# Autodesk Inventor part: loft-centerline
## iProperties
Shininess: 77.0
Angle Display Precision: 2
Document Length Units: 11269
Document Angle Units: 11279
Document Time Units: 11290
Document Mass Units: 11283
Document Length Units Precision: 3
Document Angle Units Precision: 2
Created: 2001-12
Part Number: loft-centerline
Document SubType Name: Modeling
Designer: CADSoft
Density: 0.0
Volumn: 0.0
Area: 0.0
PropertySet Name: Model Information
Control State: 0
Master: False
Checked Out: False
Author: CADSoft
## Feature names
1. Loft4
